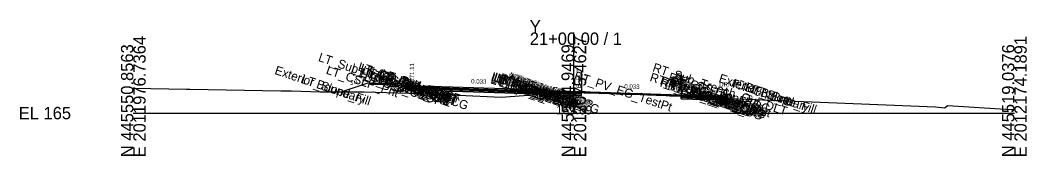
# Model space of a CAD drawing. Extents: x -26 to 3203, y -10 to 9532.
# Drawn here: x 974.3 to 1202.8, y 4990.3 to 5021.1 of the extents above; entities that cross this region are included whole.
import ezdxf

# ---------------------------------------------------------------- set-up
doc = ezdxf.new("R2010")
doc.units = 0
for name, color, linetype in [('Default', 7, 'Continuous'), ('Exist Cross Section Cell', 7, 'Continuous'), ('Exist XS Center Line Elevation Label', 7, 'Continuous'), ('Exist XS Ground Line', 7, 'Continuous'), ('Prop CMT Conc Surface', 7, 'Continuous'), ('Prop CMT Concrete Structures', 7, 'Continuous'), ('Prop CMT Pvmt Course 1', 7, 'Continuous'), ('Prop CMT Pvmt Course 1 CG', 7, 'Continuous'), ('Prop CMT Pvmt Course 1 Wedge', 7, 'Continuous'), ('Prop CMT Pvmt Course 2', 7, 'Continuous'), ('Prop CMT Pvmt Course 2 Wedge', 7, 'Continuous'), ('Prop CMT Pvmt Course 3', 7, 'Continuous'), ('Prop CMT Pvmt Course 3 Wedge', 7, 'Continuous'), ('Prop CMT Pvmt Surface', 7, 'Continuous'), ('Prop CMT Pvmt Wedge Surface 1', 7, 'Continuous'), ('Prop CMT Pvmt Wedge Surface 2', 7, 'Continuous'), ('Prop CMT Pvmt Wedge Surface 3', 7, 'Continuous'), ('Prop CMT Shear Line', 7, 'Continuous'), ('Prop CMT Shear Line Text', 7, 'Continuous'), ('Prop CMT Slope Grass', 7, 'Continuous'), ('Prop CMT Subgrade Earthwork', 7, 'Continuous'), ('Prop XS Hydro Elevations', 7, 'Continuous'), ('Prop XS Label Text', 7, 'Continuous'), ('Prop XS SE Text', 7, 'Continuous'), ('Prop XS Side Slope Text', 7, 'Continuous'), ('Scratch_Level_0', 7, 'Continuous')]:
    doc.layers.add(name, color=color, linetype=linetype)

msp = doc.modelspace()

# ---------------------------------------------------------------- linework, layer by layer
at = {"layer": 'Exist Cross Section Cell'}
for p, q in [((1100, 5000), (1100, 5018.27)), ((1000, 5000), (1100, 5000)), ((1100, 5000), (1200, 5000))]:
    msp.add_line(p, q, dxfattribs=at)
at = {"layer": 'Exist XS Ground Line'}
msp.add_lwpolyline([(1000, 5005.68), (1012.07, 5005.46), (1012.81, 5005.45), (1033.5, 5005.06), (1035.9, 5005.05), (1042.31, 5004.84), (1047.98, 5004.82), (1052.44, 5004.81), (1060.06, 5004.56), (1062.57, 5004.52), (1067.6, 5004.32), (1072.3, 5004.14), (1073.9, 5004.08), (1083.54, 5003.64), (1092.74, 5004.32), (1099.54, 5004.7), (1100, 5004.69), (1101.03, 5004.66), (1101.72, 5004.65), (1102.38, 5004.62), (1104.13, 5004.57), (1105.65, 5004.53), (1106.67, 5004.5), (1108.07, 5004.45), (1109.18, 5004.41), (1111.07, 5004.35), (1111.71, 5004.32), (1112.11, 5004.32), (1112.82, 5004.3), (1114.23, 5004.26), (1115.02, 5004.23), (1116.75, 5004.16), (1118.68, 5004.09), (1119.27, 5004.07), (1120.87, 5004), (1121.81, 5003.95), (1122.95, 5003.89), (1124.36, 5003.81), (1126.2, 5003.67), (1126.88, 5003.61), (1127.59, 5003.58), (1127.92, 5003.58), (1182.09, 5001.39), (1184.25, 5001.21), (1184.82, 5001.69), (1199.31, 5000.85), (1200, 5000.82)], dxfattribs=at)
at = {"layer": 'Prop CMT Conc Surface'}
for points in [[(1058.75, 5006.7), (1053.75, 5006.8)], [(1063.25, 5006.11), (1063.25, 5006.61), (1062.75, 5006.61)], [(1065.25, 5006.13), (1063.25, 5006.11)]]:
    msp.add_lwpolyline(points, dxfattribs=at)
at = {"layer": 'Prop CMT Concrete Structures'}
for points in [[(1053.75, 5006.47), (1053.75, 5006.8)], [(1053.75, 5006.8), (1058.75, 5006.7)], [(1058.75, 5006.37), (1053.75, 5006.47)], [(1058.75, 5006.7), (1058.75, 5006.37)], [(1065.25, 5006.13), (1063.25, 5006.11), (1063.25, 5006.61), (1062.75, 5006.61)], [(1062.75, 5006.61), (1062.75, 5005.63), (1065.25, 5005.55)], [(1065.25, 5005.55), (1065.25, 5006.13)], [(1094.54, 5005.15), (1094.53, 5005.32), (1093.78, 5005.57), (1093.02, 5005.69), (1092.26, 5005.67), (1091.51, 5005.42), (1091.5, 5005.25)], [(1091.5, 5005.25), (1094.54, 5005.15)]]:
    msp.add_lwpolyline(points, dxfattribs=at)
at = {"layer": 'Prop CMT Pvmt Course 1'}
for points in [[(1091.5, 5005.25), (1065.25, 5006.13)], [(1065.25, 5006.13), (1065.25, 5005.88)], [(1065.25, 5005.88), (1091.5, 5005)], [(1091.5, 5005.25), (1094.54, 5005.15)], [(1091.5, 5005), (1091.5, 5005.25)], [(1091.5, 5005), (1091.5, 5005.25)], [(1094.54, 5004.9), (1091.5, 5005)], [(1094.54, 5005.15), (1094.54, 5004.9)], [(1094.54, 5005.15), (1124.36, 5004.16)], [(1094.54, 5004.9), (1094.54, 5005.15)], [(1124.36, 5004.03), (1094.54, 5005.03)], [(1094.54, 5005.03), (1094.54, 5004.9), (1094.54, 5004.9)], [(1124.36, 5004.16), (1134.75, 5003.81)], [(1134.75, 5003.56), (1124.36, 5003.91)]]:
    msp.add_lwpolyline(points, dxfattribs=at)
msp.add_lwpolyline([(1091.5, 5005), (1091.5, 5005.13), (1091.5, 5005.13), (1091.5, 5005)], close=True, dxfattribs=at)
at = {"layer": 'Prop CMT Pvmt Course 1 CG'}
for points in [[(1065.25, 5005.55), (1062.25, 5005.64), (1061.93, 5005.32)], [(1061.93, 5005.32), (1065.25, 5005.21)], [(1065.25, 5005.21), (1065.25, 5005.55)]]:
    msp.add_lwpolyline(points, dxfattribs=at)
at = {"layer": 'Prop CMT Pvmt Course 1 Wedge'}
for points in [[(1094.54, 5004.9), (1094.54, 5005.03)], [(1094.54, 5005.03), (1095.28, 5005), (1099.54, 5004.86), (1099.97, 5004.85), (1101.03, 5004.81), (1101.63, 5004.79), (1101.72, 5004.79), (1102.38, 5004.77), (1104.13, 5004.71), (1105.65, 5004.66), (1106.67, 5004.62), (1108.07, 5004.58), (1109.18, 5004.54), (1111.07, 5004.48), (1111.71, 5004.46), (1112.11, 5004.44), (1112.82, 5004.42), (1114.12, 5004.37), (1114.23, 5004.37), (1115.02, 5004.34), (1116.75, 5004.29), (1118.68, 5004.22), (1119.27, 5004.2), (1120.87, 5004.15), (1121.81, 5004.12), (1122.95, 5004.08), (1124.36, 5004.03)], [(1124.36, 5003.91), (1122.95, 5003.96), (1121.81, 5003.99), (1120.87, 5004.02), (1119.27, 5004.08), (1118.68, 5004.1), (1117.05, 5004.15), (1116.75, 5004.16), (1115.02, 5004.23), (1114.23, 5004.26), (1114.12, 5004.26), (1112.82, 5004.3), (1112.11, 5004.32), (1112.06, 5004.32), (1111.71, 5004.33), (1111.07, 5004.35), (1109.51, 5004.4), (1109.18, 5004.41), (1108.07, 5004.45), (1106.67, 5004.5), (1105.75, 5004.53), (1105.65, 5004.53), (1104.13, 5004.58), (1102.38, 5004.64), (1101.72, 5004.66), (1101.63, 5004.67), (1101.03, 5004.69), (1099.97, 5004.72), (1099.54, 5004.74), (1095.28, 5004.88), (1094.54, 5004.9)]]:
    msp.add_lwpolyline(points, dxfattribs=at)
at = {"layer": 'Prop CMT Pvmt Course 2'}
for points in [[(1091.5, 5005), (1065.25, 5005.88)], [(1065.25, 5005.88), (1065.25, 5005.55)], [(1065.25, 5005.55), (1091.5, 5004.67)], [(1091.5, 5005), (1094.54, 5004.9)], [(1091.5, 5004.67), (1091.5, 5005)], [(1091.5, 5004.67), (1091.5, 5005)], [(1094.54, 5004.9), (1094.54, 5004.57)], [(1094.54, 5004.57), (1091.5, 5004.67)]]:
    msp.add_lwpolyline(points, dxfattribs=at)
at = {"layer": 'Prop CMT Pvmt Course 2 Wedge'}
for points in [[(1094.54, 5004.9), (1095.28, 5004.88), (1099.54, 5004.74), (1099.97, 5004.72), (1101.03, 5004.69), (1101.63, 5004.67), (1101.72, 5004.66), (1102.38, 5004.64), (1104.13, 5004.58), (1105.65, 5004.53), (1105.75, 5004.53)], [(1094.54, 5004.57), (1094.54, 5004.9)], [(1105.75, 5004.53), (1105.65, 5004.53), (1104.13, 5004.57), (1102.38, 5004.62), (1101.72, 5004.65), (1101.63, 5004.65), (1101.03, 5004.66), (1099.97, 5004.69), (1099.54, 5004.7), (1096.24, 5004.51), (1095.28, 5004.54), (1094.54, 5004.57)], [(1112.06, 5004.32), (1111.71, 5004.32), (1111.07, 5004.35), (1109.51, 5004.4)], [(1109.51, 5004.4), (1111.07, 5004.35)], [(1111.07, 5004.35), (1111.71, 5004.33), (1112.06, 5004.32)], [(1131.75, 5003.49), (1127.92, 5003.58), (1127.59, 5003.58), (1126.88, 5003.61), (1126.2, 5003.67), (1124.48, 5003.8), (1124.36, 5003.81), (1124.23, 5003.82), (1122.95, 5003.89), (1121.81, 5003.95), (1120.87, 5004), (1119.27, 5004.07), (1118.68, 5004.09), (1117.05, 5004.15)], [(1117.05, 5004.15), (1118.68, 5004.1)], [(1118.68, 5004.1), (1119.27, 5004.08), (1120.87, 5004.02), (1121.81, 5003.99), (1122.95, 5003.96), (1124.36, 5003.91)], [(1124.36, 5003.91), (1134.75, 5003.56)]]:
    msp.add_lwpolyline(points, dxfattribs=at)
at = {"layer": 'Prop CMT Pvmt Course 3'}
for points in [[(1091.5, 5004.67), (1065.25, 5005.55)], [(1065.25, 5005.55), (1065.25, 5005.21)], [(1065.25, 5005.21), (1091.5, 5004.34)], [(1091.5, 5004.67), (1094.54, 5004.57)], [(1091.5, 5004.34), (1091.5, 5004.67)], [(1091.5, 5004.34), (1091.5, 5004.67)], [(1094.54, 5004.24), (1091.5, 5004.34)], [(1094.54, 5004.57), (1094.54, 5004.24)], [(1094.54, 5004.24), (1101.72, 5004)], [(1124.36, 5003.24), (1134.75, 5002.9)]]:
    msp.add_lwpolyline(points, dxfattribs=at)
at = {"layer": 'Prop CMT Pvmt Course 3 Wedge'}
for points in [[(1094.54, 5004.57), (1095.28, 5004.54), (1096.24, 5004.51)], [(1094.54, 5004.42), (1094.54, 5004.57)], [(1094.54, 5004.57), (1101.72, 5004.33)], [(1096.24, 5004.51), (1095.28, 5004.46), (1094.54, 5004.42)], [(1124.36, 5003.58), (1134.75, 5003.23)]]:
    msp.add_lwpolyline(points, dxfattribs=at)
at = {"layer": 'Prop CMT Pvmt Surface'}
for points in [[(1091.5, 5005.25), (1065.25, 5006.13)], [(1091.5, 5005.25), (1094.54, 5005.15)], [(1094.54, 5005.15), (1124.36, 5004.16)], [(1124.36, 5004.16), (1134.75, 5003.81)]]:
    msp.add_lwpolyline(points, dxfattribs=at)
at = {"layer": 'Prop CMT Pvmt Wedge Surface 1'}
for points in [[(1094.54, 5005.15), (1094.54, 5004.9), (1094.54, 5004.9), (1094.54, 5005.03)], [(1094.54, 5005.03), (1124.36, 5004.03)]]:
    msp.add_lwpolyline(points, dxfattribs=at)
at = {"layer": 'Prop CMT Pvmt Wedge Surface 2'}
for points in [[(1094.54, 5005.15), (1094.54, 5004.9)], [(1094.54, 5004.9), (1124.36, 5003.91)]]:
    msp.add_lwpolyline(points, dxfattribs=at)
at = {"layer": 'Prop CMT Pvmt Wedge Surface 3'}
for points in [[(1094.54, 5005.15), (1094.54, 5004.57)], [(1094.54, 5004.57), (1101.72, 5004.33)], [(1124.36, 5003.58), (1134.75, 5003.23)]]:
    msp.add_lwpolyline(points, dxfattribs=at)
at = {"layer": 'Prop CMT Shear Line'}
msp.add_line((1134.75, 5001.17), (1134.75, 5005.76), dxfattribs=at)
at = {"layer": 'Prop CMT Slope Grass'}
msp.add_lwpolyline([(1062.75, 5006.61), (1053.25, 5006.8), (1047.3, 5004.82)], dxfattribs=at)
at = {"layer": 'Prop CMT Subgrade Earthwork'}
for p, q in [((1101.72, 5004), (1101.72, 5004.65)), ((1124.36, 5003.24), (1124.36, 5003.81))]:
    msp.add_line(p, q, dxfattribs=at)
for points in [[(1065.25, 5005.21), (1061.93, 5005.32), (1060.59, 5006.66)], [(1091.5, 5004.34), (1065.25, 5005.21)], [(1091.5, 5004.34), (1094.54, 5004.24)], [(1101.72, 5004), (1094.54, 5004.24)], [(1134.75, 5002.9), (1124.36, 5003.24)]]:
    msp.add_lwpolyline(points, dxfattribs=at)
at = {"layer": 'Prop XS Label Text'}
for p, q in [((1101.72, 5009.65), (1101.72, 5004.65)), ((1124.36, 5008.81), (1124.36, 5003.81))]:
    msp.add_line(p, q, dxfattribs=at)

# ---------------------------------------------------------------- texts
at = {"layer": 'Default'}
msp.add_text('-', height=0.0001, dxfattribs=at).set_placement((1000, 5000))
at = {"layer": 'Exist Cross Section Cell'}
for s, p in [('Y', (1090, 5018.27)), ('21+00.00 / 1', (1090, 5015.47)), ('EL 165', (974, 4998.6))]:
    msp.add_text(s, height=2.8, dxfattribs=at).set_placement(p)
for s, p in [('E 2011976.7364', (1002.8, 4990)), ('E 2012075.4627', (1102.8, 4990)), ('E 2012174.1891', (1202.8, 4990)), ('N 445550.8563', (1000, 4990)), ('N 445534.9469', (1100, 4990)), ('N 445519.0376', (1200, 4990))]:
    msp.add_text(s, height=2.8, rotation=90, dxfattribs=at).set_placement(p)
at = {"layer": 'Exist XS Center Line Elevation Label'}
msp.add_text('169.69', height=2, dxfattribs=at).set_placement((1095.97, 4999.69))
at = {"layer": 'Prop CMT Shear Line Text'}
msp.add_text('DRIVE', height=1, rotation=360, dxfattribs=at).set_placement((1132.99, 5005.97))
at = {"layer": 'Prop XS Hydro Elevations'}
msp.add_text('171.11', height=1, rotation=90, dxfattribs=at).set_placement((1063.75, 5007.11))
at = {"layer": 'Prop XS Label Text'}
for p in [(1101.62, 5005.67), (1124.26, 5004.83)]:
    msp.add_text('E. EOT', height=1, rotation=90, dxfattribs=at).set_placement(p)
at = {"layer": 'Prop XS SE Text'}
for p in [(1076.68, 5006.75), (1111.45, 5005.59)]:
    msp.add_text('0.033', height=1, rotation=358.0913, dxfattribs=at).set_placement(p)
at = {"layer": 'Prop XS Side Slope Text'}
msp.add_text('3:1', height=1, rotation=18.4349, dxfattribs=at).set_placement((1049.29, 5006.28))
at = {"layer": 'Scratch_Level_0'}
for s, p in [('LT_Sub_Trench_Out_DLT', (1041.84, 5011.85)), ('Exterior Boundary', (1031.94, 5008.89)), ('LT_CSLP_Pnt', (1043.61, 5008.96)), ('LT_CG1_Shelf_Out', (1049.18, 5008.95)), ('LT_CG_Top_Face', (1050.85, 5009.7)), ('LT_CG_Top_BOC', (1051.32, 5009.37)), ('LT_CG_Bot_BOC', (1051.35, 5008.37)), ('LT_CG_Top_Gut', (1051.77, 5008.89)), ('LT_Sub_OEOT_CG', (1052.95, 5008.26)), ('LT_CG_Bot_IE', (1055.36, 5007.79)), ('LT_PV2_OEOT', (1055.61, 5008.04)), ('LT_PV3_OEOT', (1055.61, 5007.7)), ('LT_PV1_OEOT', (1056.15, 5008.11)), ('RT_PV_EG_TestPt', (1099.89, 5007.66)), ('RT_Sub_Trench_Out_DLT', (1117.72, 5009.52)), ('LT_Slope_Fill', (1037.99, 5006.87)), ('LT_Sub_OEOP', (1052.23, 5007.5)), ('LT_Sub_OEOT', (1055.52, 5007.4)), ('LT_Sub_OEEOP', (1080.95, 5006.8)), ('LT_PV2_OEEOP', (1081.04, 5007.44)), ('LT_PV3_OEEOP', (1081.04, 5007.1)), ('LT_PV1_OEEOP', (1081.58, 5007.38)), ('LT_PV2_IEEOP', (1081.65, 5007.23)), ('LT_PV1_IEEOP', (1082.19, 5007.18)), ('LT_PV2_PGL1', (1082.53, 5006.94)), ('LT_PV3_PGL1', (1082.53, 5006.6)), ('LT_PV2_PGL', (1082.85, 5006.83)), ('LT_PV4_PGL', (1082.85, 5006.17)), ('RT_PV_IEEOP_EG', (1082.97, 5007.22)), ('LT_PV1_PGL', (1083.39, 5006.9)), ('MI_Face In', (1083.5, 5007.04)), ('RT_PV2_IEEOP', (1084.64, 5007.15)), ('RT_PV3_IEEOP', (1084.64, 5006.81)), ('MI_Face Out', (1084.98, 5007.45)), ('MI_Top Out', (1085.14, 5007.39)), ('MI_Top In', (1085.16, 5006.98)), ('RT_PV1_IEEOP', (1085.18, 5007.09)), ('RT_PV2_PGL1', (1085.52, 5006.85)), ('RT_PV3_PGL1', (1085.52, 5006.52)), ('RT_PV2_PGL', (1085.84, 5006.75)), ('RT_PV3_PGL', (1085.84, 5006.41)), ('RT_PV4_PGL', (1085.84, 5006.08)), ('MI_Bot Out', (1085.93, 5006.97)), ('MI_Crown', (1086.13, 5006.93)), ('RT_PV1_PGL', (1086.38, 5006.82)), ('RT_PV_Sub_Tie_Out', (1117.09, 5007.32)), ('RT_Sub_OEOT_CG', (1119.41, 5006.06)), ('RT_PV_OEEOP_EG', (1119.57, 5006.5)), ('RT_Sub_OEEOP', (1121.16, 5005.47)), ('RT_PV2_OEEOP', (1121.24, 5006.11)), ('RT_PV3_OEEOP', (1121.24, 5005.78)), ('RT_CG_Top_Face', (1121.3, 5007.36)), ('RT_CG1_Shelf_Out', (1121.63, 5006.55)), ('RT_PV1_OEEOP', (1121.78, 5006.06)), ('RT_CG_Bot_IE', (1121.82, 5005.58)), ('RT_PV2_OEOT', (1122.07, 5005.84)), ('RT_PV3_OEOT', (1122.07, 5005.5)), ('RT_CG_Top_Gut', (1122.23, 5006.55)), ('RT_PV1_OEOT', (1122.6, 5005.91)), ('RT_CG_Top_BOC', (1122.77, 5007.04)), ('RT_CG_Bot_BOC', (1122.8, 5006.01)), ('Exterior Boundary', (1132.75, 5007.07)), ('RT_Shld_O', (1135.85, 5005.86)), ('CSLP_Pnt', (1136.67, 5005.76)), ('RT_Sub_OEOT', (1121.98, 5005.2)), ('RT_Sub_OEOP', (1125.35, 5005.08)), ('RT_Slope_Fill', (1138.76, 5005.07))]:
    msp.add_text(s, height=2, rotation=341.5651, dxfattribs=at).set_placement(p)

doc.saveas('drawing.dxf')
